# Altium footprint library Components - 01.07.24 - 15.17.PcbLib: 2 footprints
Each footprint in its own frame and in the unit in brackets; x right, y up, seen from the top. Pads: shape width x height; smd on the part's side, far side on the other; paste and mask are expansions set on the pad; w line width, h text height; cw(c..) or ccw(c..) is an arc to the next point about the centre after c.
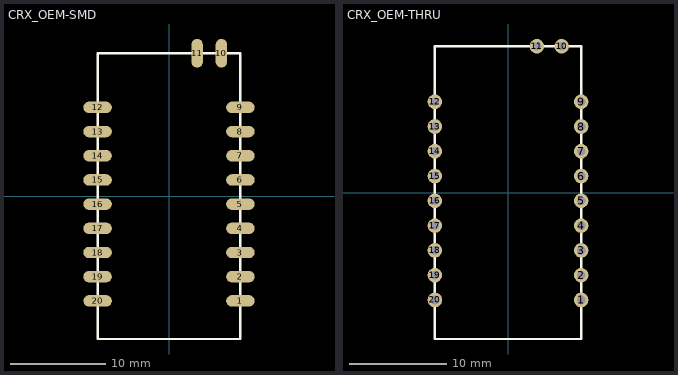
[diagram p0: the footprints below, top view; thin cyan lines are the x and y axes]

## CRX_OEM-SMD [mm] "CRX OEM Version SMD connection"
pads (20):
  oval 3x1.2 smd: 1(7.5,-11) 2(7.5,-8.46) 3(7.5,-5.92) 4(7.5,-3.38) 5(7.5,-0.84) 6(7.5,1.7) 7(7.5,4.24) 8(7.5,6.78) 9(7.5,9.32) 12(-7.5,9.32) 13(-7.5,6.78) 14(-7.5,4.24) 15(-7.5,1.7) 16(-7.5,-0.84) 17(-7.5,-3.38) 18(-7.5,-5.92) 19(-7.5,-8.46) 20(-7.493,-11)
  oval 1.2x3 smd: 10(5.5,15) 11(2.96,15)
Top Overlay:
  lines w0.254: -7.5,-15 -7.5,15 7.5,15 7.5,-15 -7.5,-15
3D body "CRX_v0.2.step": height 1.9, standoff 0.04, extent -7.5,-15 7.5,15

## CRX_OEM-THRU [mm] "CRX OEM Version Thru hole connection"
pads (20):
  round 1.5 hole 0.9: 1(7.5,-11) 2(7.5,-8.46) 3(7.5,-5.92) 4(7.5,-3.38) 5(7.5,-0.84) 6(7.5,1.7) 7(7.5,4.24) 8(7.5,6.78) 9(7.5,9.32) 10(5.5,15) 11(2.96,15) 12(-7.5,9.32) 13(-7.5,6.78) 14(-7.5,4.24) 15(-7.5,1.7) 16(-7.5,-0.84) 17(-7.5,-3.38) 18(-7.5,-5.92) 19(-7.5,-8.46) 20(-7.493,-11)
Top Overlay:
  lines w0.254: -7.5,-15 -7.5,15 7.5,15 7.5,-15 -7.5,-15
3D body "Pin Header 1x2.STEP": height 5.69, standoff -5.29, extent -8.783,2.975 -6.243,8.055
3D body "Pin Header 1x2.STEP": height 5.69, standoff -5.29, extent -8.783,-2.105 -6.243,2.975
3D body "Pin Header 1x2.STEP": height 5.69, standoff -5.29, extent -8.783,-7.185 -6.243,-2.105
3D body "Pin Header 1x2.STEP": height 5.69, standoff -5.29, extent -8.783,-12.265 -6.243,-7.185
3D body "Pin Header 1x2.STEP": height 5.69, standoff -5.29, extent 1.685,13.717 6.765,16.257
3D body "Pin Header 1x2.STEP": height 5.69, standoff -5.29, extent 6.217,2.975 8.757,8.055
3D body "Pin Header 1x2.STEP": height 5.69, standoff -5.29, extent 6.217,-2.105 8.757,2.975
3D body "Pin Header 1x2.STEP": height 5.69, standoff -5.29, extent 6.217,-7.185 8.757,-2.105
3D body "Pin Header 1x2.STEP": height 5.69, standoff -5.29, extent 6.217,-12.265 8.757,-7.185
3D body "CRX_v0.2.step": height 4.95, standoff 3.09, extent -7.5,-15 7.5,15
3D body "Pin Header 1x2.STEP": height 5.69, standoff -5.29, extent 6.217,5.515 8.757,10.595
3D body "Pin Header 1x2.STEP": height 5.69, standoff -5.29, extent -8.783,5.515 -6.243,10.595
